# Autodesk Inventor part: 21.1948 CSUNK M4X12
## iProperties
Created: 2007-03
Part Number: 21.1948 CSUNK M4X12
Material: Steel, Mild
Description: Hexagon socket countersunk head cap screws
Document SubType Name: Modeling
Standard: DIN 7991
Designer: Andy Moles
Standards Organization: DIN
Language: en-US
Size Designation: M4x8
Categories: <MemberInstance Version="R10.0.0"><Categories><Category DisplayName="Fasteners" InternalName="e4da775c-781d-43d5-af7c-5136215cf5a6" Mnemonic="FSTN"><Category Di
Density: 7.86 g/cm^3
Vendor: S
Mass: 1.45536 g
Surface Area: 2.58329 cm^2
Volume: 0.18516 cm^3
Author: Andy Moles
Revision Number: 1
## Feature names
1. Revolution1
2. Extrusion1
3. Fillet1
4. Chamfer1
